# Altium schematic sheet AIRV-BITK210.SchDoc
size A3; DocumentNumber: 3; SheetNumber: 3; SheetTotal: 7
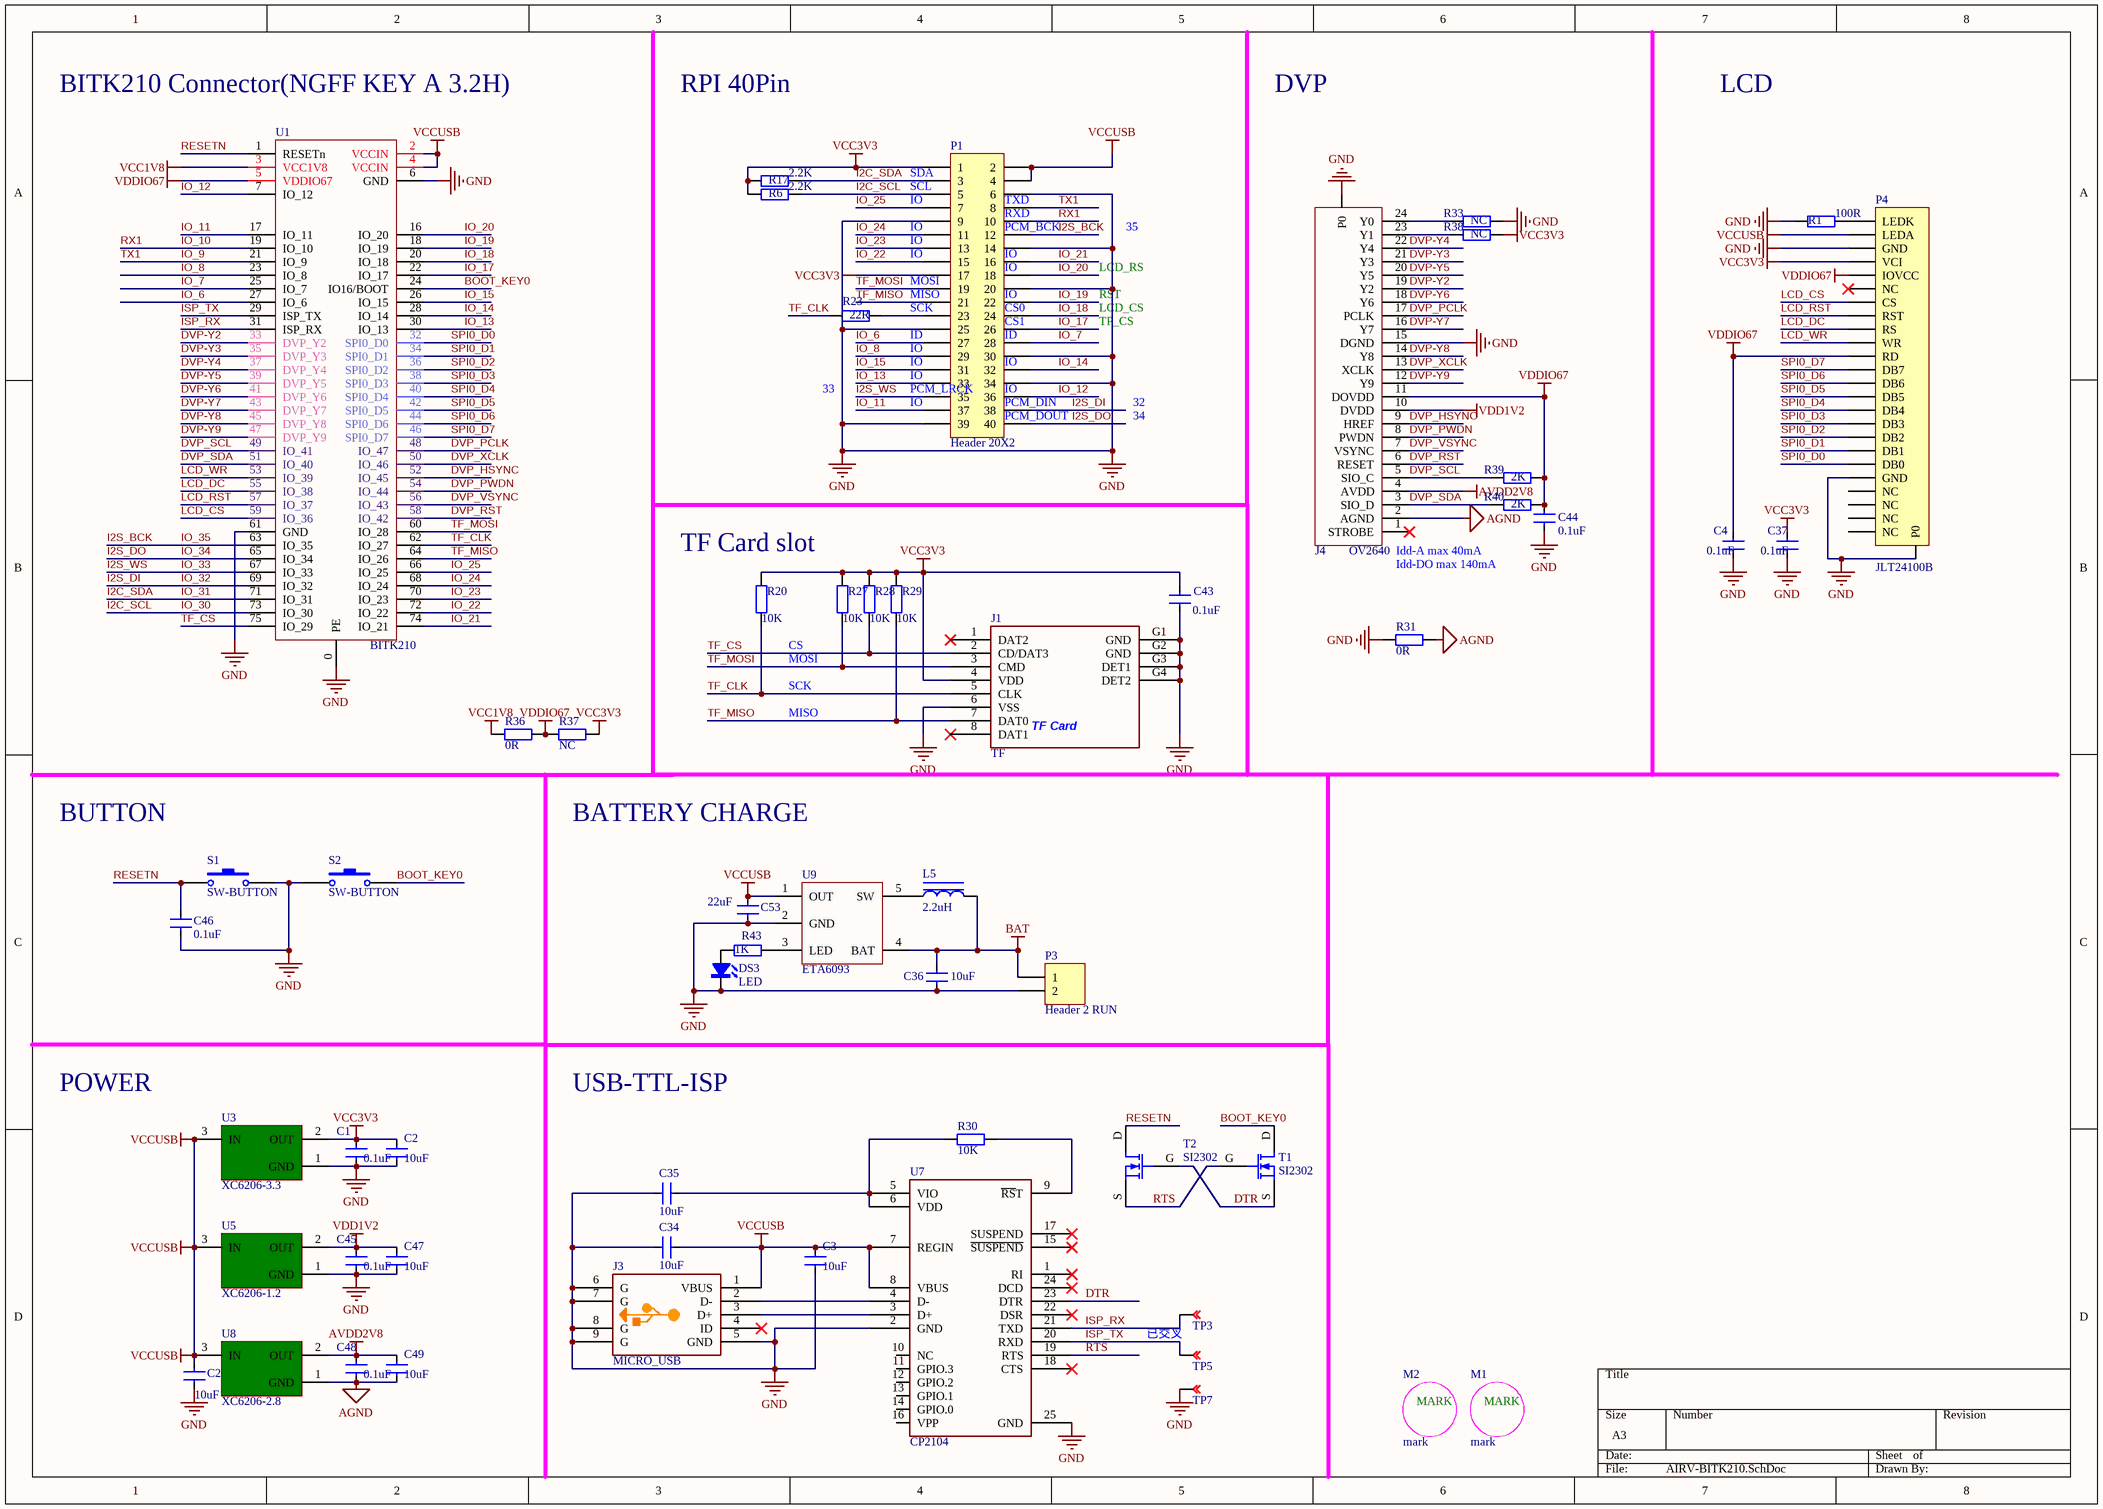
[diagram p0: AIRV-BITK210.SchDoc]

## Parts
C1  0.1uF  [C0402]
C2  10uF  [C0402]
C3  10uF  [C0402]
C4  0.1uF  [C0402]
C25  10uF  [C0402]
C34  10uF  [C0402]
C35  10uF  [C0402]
C36  10uF  [C0402]
C37  0.1uF  [C0402]
C43  0.1uF  [C0402]
C44  0.1uF  [C0402]
C45  0.1uF  [C0402]
C46  0.1uF  [C0402]
C47  10uF  [C0402]
C48  0.1uF  [C0402]
C49  10uF  [C0402]
C53  22uF  [C0603]
DS3  LED  [LED0603]
J1  TF  [TFCARD473092651]
J3  MICRO_USB  [MICROUSB]
J4  OV2640  [FFC/SM0.5-2H24-OV5640]
L5  2.2uH  [VLS2016]
M1  mark  [ZY_UR-3X2]
M2  mark  [MARKER-C]
P1  Header 20X2  [HDR2X20]
P3  Header 2 RUN  [HDR1X2]
P4  JLT24100B  [FFC/SM0.5-2H24-LCD]
R1  100R  [R0402]
R6  2.2K  [R0402]
R17  2.2K  [R0402]
R20  10K  [R0402]
R23  22R  [R0402]
R27  10K  [R0402]
R28  10K  [R0402]
R29  10K  [R0402]
R30  10K  [R0402]
R31  0R  [R0402]
R33  NC  [R0402]
R36  0R  [R0402]
R37  NC  [R0402]
R38  NC  [R0402]
R39  2K  [R0402]
R40  2K  [R0402]
R43  1K  [R0402]
S1  SW-BUTTON  [MINIBUTTON]
S2  SW-BUTTON  [MINIBUTTON]
T1  SI2302  [SOT23]
T2  SI2302  [SOT23]
TP3  TEST POINT  [TEST-POINT]  (value not drawn)
TP5  TEST POINT  [TEST-POINT]  (value not drawn)
TP7  TEST POINT  [TEST-POINT]  (value not drawn)
U1  BITK210  [NGFF_M_2-AKEY-K210]
U3  XC6206-3.3  [SOT23]
U5  XC6206-1.2  [SOT23]
U7  CP2104  [QFN24]
U8  XC6206-2.8  [SOT23]
U9  ETA6093  [SOT23-5]

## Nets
AGND: C48.1 C49.2 J4.2(AGND) R31.2 U8.1(GND)
AVDD2V8: C48.2 C49.1 J4.4(AVDD) U8.2(OUT)
BAT: C36.1 L5.1 P3.1 U9.4(BAT)
GND: C1.1 C2.2 C3.2 C4.1 C25.2 C34.1 C35.1 C36.2 C37.1 C43.2 C44.1 C45.1 C46.1 C47.2 C53.1 DS3.K J1.6(VSS) J1.G1(GND) J1.G2(GND) J1.G3(DET1) J1.G4(DET2) J3.5(GND) J3.6(G) J3.7(G) J3.8(G) J3.9(G) J4.15(DGND) J4.P0 P1.6 P1.9 P1.14 P1.20 P1.25 P1.30 P1.34 P1.39 P3.2 P4.3(GND) P4.20(GND) P4.P0 R1.1 R31.1 R33.2 S1.1 S2.2 TP7.1 U1.0(PE) U1.6(GND) U1.61(GND) U3.1(GND) U5.1(GND) U7.2(GND) U7.25(GND) U9.2(GND)
VCC1V8: R36.2 U1.3(VCC1V8)
VCC3V3: C1.2 C2.1 C37.2 C43.1 J1.4(VDD) P1.1 P1.17 P4.4(VCI) R6.2 R17.2 R20.1 R27.1 R28.1 R29.1 R37.2 R38.2 U3.2(OUT)
VCCUSB: C3.1 C25.1 C34.2 C53.2 J3.1(VBUS) P1.2 P1.4 P4.2(LEDA) U1.2(VCCIN) U1.4(VCCIN) U3.3(IN) U5.3(IN) U7.7(REGIN) U7.8(VBUS) U8.3(IN) U9.1(OUT)
VDD1V2: C45.2 C47.1 J4.10(DVDD) U5.2(OUT)
VDDIO67: C4.2 C44.2 J4.11(DOVDD) P4.5(IOVCC) P4.11(RD) R36.1 R37.1 R39.2 R40.2 U1.5(VDDIO67)
BOOT_KEY0: S2.1 T1.D U1.24(IO16/BOOT)
DTR: T1.S T2.G U7.23(DTR)
DVP-Y2: J4.19(Y2) U1.33(DVP_Y2)
DVP-Y3: J4.21(Y3) U1.35(DVP_Y3)
DVP-Y4: J4.22(Y4) U1.37(DVP_Y4)
DVP-Y5: J4.20(Y5) U1.39(DVP_Y5)
DVP-Y6: J4.18(Y6) U1.41(DVP_Y6)
DVP-Y7: J4.16(Y7) U1.43(DVP_Y7)
DVP-Y8: J4.14(Y8) U1.45(DVP_Y8)
DVP-Y9: J4.12(Y9) U1.47(DVP_Y9)
DVP_HSYNC: J4.9(HREF) U1.52(IO_45)
DVP_PCLK: J4.17(PCLK) U1.48(IO_47)
DVP_PWDN: J4.8(PWDN) U1.54(IO_44)
DVP_RST: J4.6(RESET) U1.58(IO_42)
DVP_SCL: J4.5(SIO_C) R39.1 U1.49(IO_41)
DVP_SDA: J4.3(SIO_D) R40.1 U1.51(IO_40)
DVP_VSYNC: J4.7(VSYNC) U1.56(IO_43)
DVP_XCLK: J4.13(XCLK) U1.50(IO_46)
I2C_SCL: P1.5 R6.1 U1.73(IO_30)  [also labelled IO_30]
I2C_SDA: P1.3 R17.1 U1.71(IO_31)  [also labelled IO_31]
I2S_BCK: P1.12 U1.63(IO_35)  [also labelled IO_35]
I2S_DI: P1.38 U1.69(IO_32)  [also labelled IO_32]
I2S_DO: P1.40 U1.65(IO_34)  [also labelled IO_34]
I2S_WS: P1.35 U1.67(IO_33)  [also labelled IO_33]
IO_6: P1.27 U1.27(IO_6)
IO_7: P1.28 U1.25(IO_7)
IO_8: P1.29 U1.23(IO_8)
IO_9: P1.8 U1.21(IO_9)  [also labelled TX1]
IO_10: P1.10 U1.19(IO_10)  [also labelled RX1]
IO_11: P1.37 U1.17(IO_11)
IO_12: P1.36 U1.7(IO_12)
IO_13: P1.33 U1.30(IO_13)
IO_14: P1.32 U1.28(IO_14)
IO_15: P1.31 U1.26(IO_15)
IO_17: P1.26 U1.22(IO_17)
IO_18: P1.24 U1.20(IO_18)
IO_19: P1.22 U1.18(IO_19)
IO_20: P1.18 U1.16(IO_20)
IO_21: P1.16 U1.74(IO_21)
IO_22: P1.15 U1.72(IO_22)
IO_23: P1.13 U1.70(IO_23)
IO_24: P1.11 U1.68(IO_24)
IO_25: P1.7 U1.66(IO_25)
ISP_RX: TP3.1 U1.31(ISP_RX) U7.21(TXD)
ISP_TX: TP5.1 U1.29(ISP_TX) U7.20(RXD)
LCD_CS: P4.7(CS) U1.59(IO_36)
LCD_DC: P4.9(RS) U1.55(IO_38)
LCD_RST: P4.8(RST) U1.57(IO_37)
LCD_WR: P4.10(WR) U1.53(IO_39)
RESETN: C46.2 S1.2 T2.D U1.1(RESETn)
RTS: T1.G T2.S U7.19(RTS)
SPI0_D0: P4.19(DB0) U1.32(SPI0_D0)
SPI0_D1: P4.18(DB1) U1.34(SPI0_D1)
SPI0_D2: P4.17(DB2) U1.36(SPI0_D2)
SPI0_D3: P4.16(DB3) U1.38(SPI0_D3)
SPI0_D4: P4.15(DB4) U1.40(SPI0_D4)
SPI0_D5: P4.14(DB5) U1.42(SPI0_D5)
SPI0_D6: P4.13(DB6) U1.44(SPI0_D6)
SPI0_D7: P4.12(DB7) U1.46(SPI0_D7)
TF_CLK: J1.5(CLK) R20.2 R23.1 U1.62(IO_27)
TF_CS: J1.2(CD/DAT3) R28.2 U1.75(IO_29)
TF_MISO: J1.7(DAT0) P1.21 R29.2 U1.64(IO_26)
TF_MOSI: J1.3(CMD) P1.19 R27.2 U1.60(IO_28)
NetC35_2: C35.2 R30.2 U7.5(VIO) U7.6(VDD)
NetDS3_A: DS3.A R43.2
NetJ3_2: J3.2(D-) U7.4(D-)
NetJ3_3: J3.3(D+) U7.3(D+)
NetJ4_23: J4.23(Y1) R38.1
NetJ4_24: J4.24(Y0) R33.1
NetL5_2: L5.2 U9.5(SW)
NetP1_23: P1.23 R23.2
NetP4_1: P4.1(LEDK) R1.2
NetR30_1: R30.1 U7.9(~{RS}T)
NetR43_1: R43.1 U9.3(LED)

Not connected (* = marked no-connect by the designer): J1 1(DAT2)* 8(DAT1)*; J3 4(ID)*; J4 1(STROBE)*; P4 6(NC)* 21(NC) 22(NC) 23(NC) 24(NC); U7 1(RI)* 10(NC) 11(GPIO.3) 12(GPIO.2) 13(GPIO.1) 14(GPIO.0) 15(~{SUSPEND})* 16(VPP) 17(SUSPEND)* 18(CTS)* 22(DSR)* 24(DCD)*

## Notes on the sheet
- BITK210 Connector(NGFF KEY A 3.2H)
- RPI 40Pin
- DVP
- LCD
- (near P1) SDA
- (near P1) SCL
- (near P1) IO
- (near P1) TXD
- (near P1) RXD
- (near P1) PCM_BCK
- 35
- (near P1) MOSI
- (near P1) MISO
- (near P1) SCK
- (near P1) CS0
- LCD_RS
- RST
- LCD_CS
- ID
- (near P1) CS1
- (near P1) ID
- TP_CS
- 33
- (near P1) PCM_LRCK
- (near P1) PCM_DIN
- (near P1) PCM_DOUT
- 34
- 32
- TF Card slot
- (near J4) Idd-A max 40mA
- (near J4) Idd-DO max 140mA
- CS
- MOSI
- MISO
- SCK
- BUTTON
- BATTERY CHARGE
- POWER
- USB-TTL-ISP
- 已交叉

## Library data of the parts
C1-C4 C25 C34-C37 C43-C49 C53 = CAP: 普通小电容
J1 = TF_473092651
J4 = OV5640: Header, 24-Pin
L5 = L: 普通电感
P1 = Header 20X2: Header, 20-Pin, Dual row
P3 = Header 2: Header, 2-Pin
R1 R6 R17 R20 R23 R27-R31 R33 R36-R40 R43 = RES: 普通电阻
T1 T2 = MOS-N: pin to pad: D>3 G>1 S>2
TP3 TP5 TP7 = TP: Description
U3 U5 U8 = XC6206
